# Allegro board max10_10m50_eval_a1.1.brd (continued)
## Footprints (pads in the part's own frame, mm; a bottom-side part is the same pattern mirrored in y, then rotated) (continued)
QFN56
  oval 0.813x0.279 smd: 1(-3.9,3.25) 2(-3.9,2.75) 3(-3.9,2.25) 4(-3.9,1.75) 5(-3.9,1.25) 6(-3.9,0.75) 7(-3.9,0.25) 8(-3.9,-0.25) 9(-3.9,-0.75) 10(-3.9,-1.25) 11(-3.9,-1.75) 12(-3.9,-2.25) 13(-3.9,-2.75) 14(-3.9,-3.25) 29(3.9,-3.25) 30(3.9,-2.75) 31(3.9,-2.25) 32(3.9,-1.75) 33(3.9,-1.25) 34(3.9,-0.75) 35(3.9,-0.25) 36(3.9,0.25) 37(3.9,0.75) 38(3.9,1.25) 39(3.9,1.75) 40(3.9,2.25) 41(3.9,2.75) 42(3.9,3.25)
  oval 0.279x0.813 smd: 15(-3.25,-3.9) 16(-2.75,-3.9) 17(-2.25,-3.9) 18(-1.75,-3.9) 19(-1.25,-3.9) 20(-0.75,-3.9) 21(-0.25,-3.9) 22(0.25,-3.9) 23(0.75,-3.9) 24(1.25,-3.9) 25(1.75,-3.9) 26(2.25,-3.9) 27(2.75,-3.9) 28(3.25,-3.9) 43(3.25,3.9) 44(2.75,3.9) 45(2.25,3.9) 46(1.75,3.9) 47(1.25,3.9) 48(0.75,3.9) 49(0.25,3.9) 50(-0.25,3.9) 51(-0.75,3.9) 52(-1.25,3.9) 53(-1.75,3.9) 54(-2.25,3.9) 55(-2.75,3.9) 56(-3.25,3.9)
  rect 5.842x5.842 smd: 57(0,0)
SENSE
  rect 0.305x0.406 smd: 1(0,0.254) 2(0,-0.254)
SI510
  rect 1.55x1.95 smd: 1(-2.54,-2.1) 2(0,-2.1) 3(2.54,-2.1) 4(2.54,2.1) 5(0,2.1) 6(-2.54,2.1)
SO16_WIDE
  oval 0.6x2.2 smd: 1(-4.445,-4.599) 2(-3.175,-4.599) 3(-1.905,-4.599) 4(-0.635,-4.599) 5(0.635,-4.599) 6(1.905,-4.599) 7(3.175,-4.599) 8(4.445,-4.599) 9(4.445,4.599) 10(3.175,4.599) 11(1.905,4.599) 12(0.635,4.599) 13(-0.635,4.599) 14(-1.905,4.599) 15(-3.175,4.599) 16(-4.445,4.599)
SOT23-6L
  rect 0.6x1.4 smd: 1(-0.95,-1.3) 2(0,-1.3) 3(0.95,-1.3) 4(0.95,1.3) 5(0,1.3) 6(-0.95,1.3)
SOT-143
  rect 0.864x0.889 smd: 1(-0.914,0.762)
  rect 0.864x0.508 smd: 2(-0.914,-0.965) 3(0.94,-0.965) 4(0.94,0.965)
SW-PUSH-8X8
  rect 1.245x1.245 hole 0.762: 1(0,0)
  round 1.245 hole 0.762: 2(2.54,0) 3(5.08,0) 4(0,6.096) 5(2.54,6.096) 6(5.08,6.096)
TEST_PAD_SMT
  round 1.016 smd: 1(0,0)
TEST_PAD_SMT_10MIL
  round 0.254 smd: 1(0,0)
unnamed
  round 1.016 smd: 1(0,0)
unnamed#2
  round 6.35 hole 3.175: (0,0)
UQFN16
  rect 0.559x0.203 smd: 1(-1.05,1) 2(-1.05,0.6) 3(-1.05,0.2) 4(-1.05,-0.2) 5(-1.05,-0.6) 6(-1.05,-1) 9(1.05,-1) 10(1.05,-0.6) 11(1.05,-0.2) 12(1.05,0.2) 13(1.05,0.6) 14(1.05,1)
  rect 0.203x0.559 smd: 7(-0.2,-1.175) 8(0.2,-1.175) 15(0.2,1.175) 16(-0.2,1.175)
WURTH_MSOP8
  rect 1.016x0.406 smd: 1(-2.4,0.975) 2(-2.4,0.325) 3(-2.4,-0.325) 4(-2.4,-0.975) 5(2.4,-0.975) 6(2.4,-0.325) 7(2.4,0.325) 8(2.4,0.975)
WURTH_USB_MINI-B
  oval 1.016x1.143 hole 0.711: 1(-1.6,0.9) 2(-0.8,-0.3) 3(0,0.9) 4(0.8,-0.3) 5(1.6,0.9)
  oval 1.626x2.616 hole 0.914x1.905: 6(-3.65,0) 7(3.65,0) 8(-3.65,-4.65) 9(3.65,-4.65)
XTAL_FA-128
  rect 0.94x0.838 smd: 1(-0.725,-0.575) 2(0.725,-0.575) 3(0.725,0.575) 4(-0.725,0.575)

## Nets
1.2V_CORE: C221.1 C222.1 C223.1 C224.2 C225.2 C226.2 C227.2 C228.2 C229.2 C230.2 C231.2 L8.1 R238.2 U1.J7(VCCINT) U1.K11(VCC#K11) U1.K13(VCC#K13) U1.L10(VCC#L10) U1.L11(VCC#L11) U1.L12(VCC#L12) U1.M11(VCC#M11) U1.M12(VCC#M12) U1.M13(VCC#M13) U1.N10(VCC#N10) U1.N12(VCC#N12)
1.2V_CORE_ENABLE: C174.1 R252.1 R283.1 U21.18(ENABLE)
1.2V_CORE_POK: R239.1 U4.Y11(IOB4_36) U21.17(POK)
1.2V_CORE_SENSE: C112.2 C113.1 C114.1 C116.1 C248.1 C249.1 R238.1 R240.2 U21.4(VOUT#4) U21.5(VOUT#5) U21.6(VOUT#6) U21.7(VOUT#7)
1.2V_CORE_VFB: C112.1 R240.1 R243.2 U21.14(VFB)
1.2V_LED: D11.2(CATHODE) U4.Y9(IOB4_51)
1.2V_LED_R: D11.1(ANODE) R278.2
1.2V_VCCD_PLL: C121.1 C122.1 C145.2 C146.2 C147.2 C148.2 L8.2 U1.G7(VCCD_PLL3) U1.G16(VCCD_PLL2) U1.T7(VCCD_PLL1) U1.U16(VCCD_PLL4)
1.2V_VCCIO: C4.1 C6.1 C13.1 C14.1 C15.1 C16.1 C17.1 C18.1 C19.1 C20.1 C21.1 C22.1 C23.1 C24.1 C25.1 C118.1 C149.2 C194.1 C208.2 C209.1 C232.1 C233.2 C234.2 C235.2 C236.2 C241.1 C242.1 C244.1 C245.1 C246.1 C250.1 R7.1 R9.2 R10.2 R29.2 R30.2 R181.1 R182.1 R184.1 R185.1 R195.1 R196.1 R198.1 R202.1 R285.2 R315.2 U1.H16(VCCIO6#H16) U1.J17(VCCIO6#J17) U1.K16(VCCIO6#K16) U1.K17(VCCIO6#K17) U1.L16(VCCIO6#L16) U1.M17(VCCIO6#M17) U1.N16(VCCIO5#N16) U1.N17(VCCIO6#N17) U1.P16(VCCIO5#P16) U1.R16(VCCIO5#R16) U1.R17(VCCIO5#R17) U1.T17(VCCIO5#T17) U2.B5(VDD2#B5) U2.C7(VDDQ#C7) U2.C10(VDDQ#C10) U2.D2(VDD2#D2) U2.D5(VDDQ#D5) U2.E9(VDDQ#E9) U2.F1(VDDCA#F1) U2.F10(VDDQ#F10) U2.G1(VDD2#G1) U2.H1(VDDCA#H1) U2.H6(VDDQ#H6) U2.J6(VDDQ#J6) U2.J7(VDD2#J7) U2.K6(VDDQ#K6) U2.M10(VDDQ#M10) U2.N2(VDDCA#N2) U2.N9(VDDQ#N9) U2.P2(VDD2#P2) U2.P5(VDDQ#P5) U2.R7(VDDQ#R7) U2.R10(VDDQ#R10) U2.T5(VDD2#T5) U22.6(VOUT#6) U22.7(VOUT#7)
1.2V_VCCIO_ENABLE: C119.1 R241.1 R242.1 U22.10(ENABLE)
1.2V_VCCIO_VFB: C208.1 R285.1 R286.2 U22.4(VFB)
1.8V: C26.1 C27.1 C105.1 C106.1 C107.1 C196.1 C197.1 C217.1 C218.1 C219.1 C243.1 C247.1 L1.1 L2.1 L3.1 L6.2 R1.2 R64.1 R68.1 R89.1 R91.1 R92.1 R235.1 R241.2 R246.1 R279.2 R305.1 R308.1 U1.N6(VCCIO2#N6) U1.N7(VCCIO2#N7) U1.P7(VCCIO2#P7) U1.R6(VCCIO2#R6) U2.B6(VDD1#B6) U2.C1(VDD1#C1) U2.R1(VDD1#R1) U2.T6(VDD1#T6) U20.7(VOUT#7) U20.8(VOUT#8)
1.8V_AVDD: C52.1 C53.1 C54.1 C55.1 L3.2 R119.1 U3.15(AVDD#15) U3.19(AVDD#19) U3.25(AVDD#25)
1.8V_DVDD: C44.1 C45.1 C46.1 C47.1 C48.1 L1.2 U3.1(DVDD#1) U3.11(DVDD#11) U3.31(DVDD#31) U3.51(DVDD#51)
1.8V_ENABLE: C176.1 R257.2 U20.12(ENABLE)
1.8V_MIPITX: C29.1 J1.32 J1.33 R64.2
1.8V_OV10640: C171.1 J2.4 J2.5 R246.2
1.8V_PVDD: C49.1 C50.1 C51.1 L2.2 U3.12(PVDD) U3.13(BGVDD)
1.8V_SI5338: C88.1 L6.1 U14.20(VDDO0)
2.5V: C72.1 C73.1 C76.1 C77.1 C144.2 C211.1 C213.1 C216.2 C239.2 C251.1 J12.1 J12.2 J13.1 J13.2 R21.1 R24.1 R25.1 R137.1 R139.1 R200.2 R205.2 R236.1 R283.2 R290.2 U1.T9(VCCIO3#T9) U1.T10(VCCIO3#T10) U1.T11(VCCIO3#T11) U1.T12(VCCIO4#T12) U1.T13(VCCIO4#T13) U1.U8(VCCIO3#U8) U1.U9(VCCIO3#U9) U1.U11(VCCIO4#U11) U1.U12(VCCIO4#U12) U1.U14(VCCIO4#U14) U4.C9(VCCIO2#C9) U4.C10(VCCIO2#C10) U4.C11(VCCIO2#C11) U4.D10(VCCIO2#D10) U4.D11(VCCINT#D11) U4.K4(VCCINT#K4) U4.L17(VCCINT#L17) U4.U11(VCCINT#U11) U19.6(VOUT#6) U19.7(VOUT#7)
2.5V_CORE: L7.1 R236.2
2.5V_ENABLE: C175.1 R255.1 R282.1 U19.10(ENABLE)
2.5V_LED_R: D10.1(ANODE) R200.1
2.5V_VCCA: C108.1 C109.1 C124.2 C206.2 C237.2 C238.2 L7.2 R267.2 U1.H7(VCCA_ADC) U1.H8(VCCA3) U1.H15(VCCA2) U1.R8(VCCA1) U1.T15(VCCA4)
3.3V: C58.2 C63.1 C64.1 C65.1 C66.1 C67.1 C68.1 C69.1 C70.1 C74.1 C75.1 C78.1 C79.1 C80.1 C81.1 C91.1 C92.1 C93.1 C155.2 C156.2 C169.2 C170.1 J6.4 J7.4 J8.6 J8.12 J9.6 J9.12 J14.5(IO5) J14.6(IO6) L4.1 L5.2 L9.1 R27.1 R28.1 R61.1 R98.1 R99.1 R100.1 R101.1 R127.1 R128.1 R136.1 R138.1 R140.1 R141.1 R142.1 R145.2 R146.2 R147.1 R183.1 R186.1 R187.1 R188.1 R189.1 R190.1 R191.1 R192.1 R193.1 R194.1 R203.1 R204.1 R223.2 R239.2 R244.1 R245.1 R247.1 R248.2 R278.1 R281.2 R303.1 R306.1 R309.1 U1.F9(VCCIO8#F9) U1.F11(VCCIO8#F11) U1.F12(VCCIO7#F12) U1.F14(VCCIO7#F14) U1.G10(VCCIO8#G10) U1.G11(VCCIO8#G11) U1.G12(VCCIO7#G12) U1.G13(VCCIO7#G13) U1.G14(VCCIO7#G14) U1.K7(VCCIO1A#K7) U1.L6(VCCIO1A#L6) U1.L7(VCCIO1B#L7) U1.M6(VCCIO1B#M6) U4.J18(VCCIO3#J18) U4.K3(VCCIO1#K3) U4.K17(VCCIO3#K17) U4.K18(VCCIO3#K18) U4.L3(VCCIO1#L3) U4.L4(VCCIO1#L4) U4.L18(VCCIO3#L18) U4.M3(VCCIO1#M3) U4.U10(VCCIO4#U10) U4.V10(VCCIO4#V10) U4.V11(VCCIO4#V11) U4.V12(VCCIO4#V12) U5.4(VCC) U7.3(AVCC#3) U7.7(AVCC#7) U7.11(VCC#11) U7.17(VCC#17) U7.27(VCC#27) U7.32(VCC#32) U7.43(VCC#43) U7.55(VCC#55) U8.5(VDD) U9.5(VDD) U10.5(VDD) U11.5(VDD) U17.4(VOUT#4) U17.5(VOUT#5) U17.6(VOUT#6) U17.7(VOUT#7) U23.2(VCC)
3.3V_DVDD: C56.1 C57.1 L4.2 R120.2 R121.2 R122.2 U3.29(DVDD_3V)
3.3V_EN: C207.1 R279.1 R280.1 R284.2 U17.18(ENABLE)
3.3V_MIPITX: C30.1 J1.34 J1.35 J1.36 R61.2
3.3V_OV5640: C173.1 J3.16 R248.1
3.3V_OV10640: C172.1 J2.1 J2.2 J2.3 R247.2
3.3V_POK: R281.1 R282.2 U17.17(POK)
3.3V_SI510: C240.1 L9.2 R214.1 U15.6(VDD)
3.3V_SI5338: C82.1 C83.1 C84.1 C85.1 C86.1 L5.1 U14.7(VDD1) U14.11(VDDO3) U14.15(VDDO2) U14.16(VDDO1) U14.24(VDD2)
3.3V_VFB: C91.2 R223.1 R229.2 U17.14(VFB)
5V: C42.1 C43.1 D1.8 D2.8 J4.18(5V_VCC) J11.2 R114.2 R115.2 R199.1 R253.1 R254.1 R258.1 R260.1 R280.2 R289.1 R292.2 R293.1
5V_DCIN: J10.2 R217.1 R222.2 R224.2 U18.2(VDD) V1.2(SNS)
5V_FB: R226.1 R233.2 U18.12(FB)
5V_GATE: R225.2 R231.2 U18.9(GATE)
5V_IMON: R232.2 U18.13(IMON)
5V_LED_R: D9.1(ANODE) R199.2
5V_MONITOR: C94.1 C95.2 J11.1 R226.2 R227.2 R228.1 R292.1 U16.1(S1) U16.2(S2) U16.3(S3) U18.8(SOURCE)
5V_N: U18.15(SENSE-) V2.1(RSNS)
5V_OV: R224.1 R230.2 U18.4(OV)
5V_P: U18.16(SENSE+) V1.1(RSNS)
5V_PG: R227.1 U18.10(PG)
5V_R1.2CORE: C111.1 C120.1 R252.2 R253.2 U21.10(TST2) U21.11(TST1) U21.12(TST0) U21.16(AVIN) U21.19(PVIN#19) U21.20(PVIN#20)
5V_R1.2VCCIO: C115.1 C210.2 R242.2 R254.2 U22.11(AVIN) U22.12(PVIN)
5V_R1.8: C104.1 R257.1 R258.2 U20.9(VS2) U20.10(VS1) U20.11(VS0) U20.13(AVIN) U20.14(PVIN)
5V_R2.5: C212.2 C215.1 R255.2 R289.2 U19.11(AVIN) U19.12(PVIN)
5V_R3.3: C90.1 C96.1 R260.2 U17.10(TST2) U17.11(TST1) U17.12(TST0) U17.16(AVIN) U17.19(PVIN#19) U17.20(PVIN#20)
5V_UV: R264.2 U18.3(UV) U18.11(/FLT)
GND: C1.2 C3.2 C8.2 C9.2 C10.2 C11.2 C13.2 C14.2 C15.2 C16.2 C17.2 C18.2 C19.2 C20.2 C21.2 C22.2 C23.2 C24.2 C25.2 C26.2 C27.2 C28.2 C29.2 C30.2 C31.2 C32.2 C33.2 C34.2 C35.2 C36.2 C37.2 C38.2 C39.2 C40.2 C41.2 C42.2 C43.2 C44.2 C45.2 C46.2 C47.2 C48.2 C49.2 C50.2 C51.2 C52.2 C53.2 C54.2 C55.2 C56.2 C57.2 C58.1 C59.2 C60.2 C61.2 C62.2 C63.2 C64.2 C65.2 C66.2 C67.2 C68.2 C69.2 C70.2 C71.2 C72.2 C73.2 C74.2 C75.2 C76.2 C77.2 C78.2 C79.2 C80.2 C81.2 C82.2 C83.2 C84.2 C85.2 C86.2 C87.1 C88.2 C89.1 C90.2 C92.2 C93.2 C94.2 C95.1 C96.2 C97.2 C98.1 C99.2 C104.2 C106.2 C107.2 C108.2 C109.2 C111.2 C113.2 C114.2 C115.2 C116.2 C118.2 C119.2 C120.2 C121.2 C122.2 C124.1 C144.1 C145.1 C146.1 C147.1 C148.1 C149.1 C155.1 C156.1 C169.1 C170.2 C171.2 C172.2 C173.2 C174.2 C175.2 C176.2 C194.2 C196.2 C197.2 C206.1 C207.2 C209.2 C210.1 C211.2 C212.1 C213.2 C215.2 C217.2 C218.2 C219.2 C220.2 C221.2 C222.2 C223.2 C224.1 C225.1 C226.1 C227.1 C228.1 C229.1 C230.1 C231.1 C232.2 C233.1 C234.1 C235.1 C236.1 C237.1 C238.1 C239.1 C240.2 C243.2 C244.2 C245.2 C246.2 C247.2 C248.2 C249.2 C250.2 C251.2 D1.7 D2.7 D9.2(CATHODE) D10.2(CATHODE) J1.3 J1.4 J1.8 J1.15 J1.18 J1.21 J1.24 J1.27 J1.30 J1.31 J1.G1(SP1) J1.G2(SP2) J1.G3(SP3) J1.G4(SP4) J2.6 J2.7 J2.10 J2.13 J2.16 J2.19 J2.22 J2.29 J2.33 J2.34 J2.G1(SP1) J2.G2(SP2) J2.G3(SP3) J2.G4(SP4) J3.3 J3.4 J3.7 J3.10 J3.17 J3.18 J4.2(TMDS_DATA_SHLD2) J4.5(TMDS_DATA_SHLD1) J4.8(TMDS_DATA_SHLD0) J4.11(TMDS_DATA_SHLD_CLK) J4.17(DDC_CEC_GND) J4.G1(MTG1) J4.G2(MTG2) J4.G3(MTG3) J4.G4(MTG4) J5.5(GND) J6.2 J6.10 J7.10 J8.5 J8.11 J9.5 J9.11 J10.1 J10.3 J12.7 J12.8 J12.13 J12.14 J12.19 J12.20 J13.7 J13.8 J13.13 J13.14 J13.19 J13.20 J14.11(IO11) J14.12(IO12) R2.1 R8.1 R11.1 R12.1 R18.1 R20.1 R22.1 R23.1 R31.1 R32.1 R34.1 R35.2 R38.2 R39.2 R43.1 R45.1 R51.2 R52.2 R55.1 R57.1 R63.2 R66.1 R111.1 R112.1 R113.1 R116.1 R117.2 R118.2 R124.2 R125.1 R126.2 R134.1 R135.1 R144.1 R180.1 R221.1 R228.2 R229.1 R230.1 R232.1 R233.1 R243.1 R269.1 R284.1 R286.1 R291.1 R315.1 S1.1 S1.2 S2.1 S2.2 S3.1 S3.2 S4.1 S4.2 S6.1 S6.2 S7.1 S7.2 SW1.1(A1) SW1.2(A2) SW1.3(A3) SW1.4(A4) SW2.1(A1) SW2.2(A2) SW2.3(A3) SW2.4(A4) SW3.1(NO1) SW3.6(NO2) TP1.1(TP) TP2.1(TP) TP3.1(TP) TP4.1(TP) TP5.1(TP) TP6.1(TP) U1.A1(GND#A1) U1.A22(GND#A22) U1.AA4(GND#AA4) U1.AA18(GND#AA18) U1.AB1(GND#AB1) U1.AB22(GND#AB22) U1.B6(GND#B6) U1.B9(GND#B9) U1.B13(GND#B13) U1.B18(GND#B18) U1.B20(DIFFIO_RX_R62P) U1.B21(DIFFIO_RX_R60N) U1.C20(DIFFIO_RX_R56P) U1.C21(TBD6) U1.D4(GND#D4) U1.D11(GND#D11) U1.D16(GND#D16) U1.D19(DIFFIO_RX_R56N) U1.D20(GND#D20) U1.E2(GND#E2) U1.E5(NC1) U1.E6(DIFFIO_RX_T52N/PLL_T_CLKOUTN) U1.E7(GND#E7) U1.E17(DIFFIO_RX_R59N) U1.E19(DIFFIO_RX_R53P) U1.E20(DIFFIO_RX_R54N) U1.F6(NC2) U1.F10(GND#F10) U1.F13(GND#F13) U1.F17(DIFFIO_RX_R59P) U1.F18(DIFFIO_RX_R53N) U1.F19(DIFFIO_RX_R54P) U1.F20(DIFFIO_RX_R48N) U1.F21(DIFFIO_RX_R48P) U1.G5(ANAIN1) U1.G6(GND#G6) U1.G8(GND#G8) U1.G15(GND#G15) U1.G17(DIFFIO_RX_R69N/PLL_R_CLKOUTN) U1.G18(GND#G18) U1.G19(DIFFIO_RX_R42N) U1.G20(DIFFIO_RX_R42P) U1.G21(GND#G21) U1.H5(REFGND) U1.H11(DIFFIO_RX_T40N/CLK5N) U1.H17(DIFFIO_RX_R69P/PLL_R_CLKOUTP) U1.J2(GND#J2) U1.J5(ANAIN2) U1.J6(GND#J6) U1.J8(DIFFIO_RX_L3N/ADC1IN3) U1.J9(DIFFIO_RX_L3P/ADC1IN4) U1.J16(GND#J16) U1.J19(GND#J19) U1.J20(DIFFIO_RX_R64P/DQ3R) U1.K3(GND#K3) U1.K4(DIFFIO_RX_L8N/ADC2IN7) U1.K5(DIFFIO_RX_L7N/ADC1IN7) U1.K6(DIFFIO_RX_L7P/ADC1IN8) U1.K10(GND#K10) U1.K12(GND#K12) U1.L5(GND#L5) U1.L13(GND#L13) U1.L17(GND#L17) U1.L19(DIFFIO_RX_R52P/DQ2R) U1.L21(GND#L21) U1.L22(DIFFIO_RX_R34N) U1.M7(GND#M7) U1.M8(DIFFIO_RX_L36N/CLK1N) U1.M10(GND#M10) U1.M16(GND#M16) U1.M19(GND#M19) U1.M21(DIFFIO_RX_R34P) U1.M22(DIFFIO_RX_R35N) U1.N4(DIFFIO_RX_L28N/CLK0N) U1.N11(GND#N11) U1.N13(GND#N13) U1.N15(DIFFIO_RX_R38N/CLK2N) U1.N21(DIFFIO_RX_R35P) U1.P2(GND#P2) U1.P3(DIFFIO_RX_L38N/DPCLK0) U1.P6(GND#P6) U1.P17(GND#P17) U1.P18(DIFFIO_RX_R32N/DQSN1R) U1.P19(DIFFIO_RX_R33P/DQ1R) U1.P20(DIFFIO_RX_R33N/DQ1R) U1.R3(DIFFIO_RX_L38P/DPCLK1) U1.R19(GND#R19) U1.R21(GND#R21) U1.R22(TBD5) U1.T4(GND#T4) U1.T5(DIFFIO_RX_L59N/PLL_L_CLKOUTN) U1.T6(DIFFIO_RX_L59P/PLL_L_CLKOUTP) U1.T8(GND#T8) U1.T14(GND#T14) U1.T16(GND#T16) U1.T20(DIFFIO_RX_R28P/DQ1R) U1.U10(GND#U10) U1.U13(GND#U13) U1.U21(DIFFIO_RX_R29P) U1.U22(DIFFIO_RX_R29N) U1.V2(GND#V2) U1.V6(GND#V6) U1.V18(DIFFIO_RX_R19P) U1.V19(GND#V19) U1.V20(DIFFIO_RX_R23P) U1.W21(GND#W21) U1.Y9(GND#Y9) U1.Y12(GND#Y12) U1.Y15(GND#Y15) U2.C2(VSS#C2) U2.C5(VSS#C5) U2.C6(VSSQ#C6) U2.C9(VSSQ#C9) U2.D1(VSS#D1) U2.D10(VSSQ#D10) U2.E1(VSSCA#E1) U2.E10(VSSQ#E10) U2.F5(VSSQ#F5) U2.G10(VSSQ#G10) U2.H2(VSS#H2) U2.J1(VSSCA#J1) U2.J5(VSSQ#J5) U2.J8(VSS#J8) U2.L10(VSSQ#L10) U2.M5(VSSQ#M5) U2.N1(VSSCA#N1) U2.N10(VSSQ#N10) U2.P1(VSS#P1) U2.P10(VSSQ#P10) U2.R2(VSS#R2) U2.R5(VSS#R5) U2.R6(VSSQ#R6) U2.R9(VSSQ#R9) U3.65(EPAD_GND) U4.C8(GNDIO#C8) U4.C12(GNDIO#C12) U4.C13(GNDIO#C13) U4.D9(GNDIO#D9) U4.D12(GNDINT#D12) U4.H3(GNDIO#H3) U4.H18(GNDIO#H18) U4.J3(GNDIO#J3) U4.J4(GNDINT#J4) U4.J17(GNDIO#J17) U4.M4(GNDIO#M4) U4.M17(GNDINT#M17) U4.M18(GNDIO#M18) U4.N3(GNDIO#N3) U4.N18(GNDIO#N18) U4.U9(GNDIO#U9) U4.U12(GNDINT#U12) U4.V8(GNDIO#V8) U4.V9(GNDIO#V9) U4.V13(GNDIO#V13) U5.1(GND) U6.3(GND) U7.6(AGND#6) U7.10(AGND#10) U7.12(GND#12) U7.14(RESERVED) U7.26(GND#26) U7.28(GND#28) U7.41(GND#41) U7.53(GND#53) U7.56(GND#56) U7.57(EXPOSED_PAD) U8.2(GND) U9.2(GND) U10.2(GND) U11.2(GND) U14.3(CLKIN) U14.4(I2C_LSB) U14.6(FDBK_N) U14.23(RSVD_GND) U14.25(EPAD) U15.3(GND) U17.2(PGND#2) U17.3(PGND#3) U17.8(PGND#8) U17.9(PGND#9) U17.15(AGND) U17.25(PGND#25) U17.26(PGND#26) U18.7(GND) U19.2(PGND) U19.5(AGND) U20.2(PGND#2) U20.3(PGND#3) U20.6(AGND) U21.2(PGND#2) U21.3(PGND#3) U21.8(PGND#8) U21.9(PGND#9) U21.15(AGND) U21.25(PGND#25) U21.26(PGND#26) U22.2(PGND) U22.5(AGND) U23.10(VSS) Y1.2 Y1.4 Y2.2 Y2.4
GND_EARTH: C59.1 J5.6(SHELL1) J5.7(SHELL2) J5.8(SHELL3) J5.9(SHELL4) R125.2
VBUS_5V: C220.1 J5.1(VBUS) J11.3 R133.1 R293.2
24M_XTALIN: C60.1 U7.5(XTALIN) Y1.1
24M_XTALOUT: C61.1 U7.4(XTALOUT) Y1.3
ADC_VREF: R267.1 U1.H6(ADC_VREF)
C_USB_MAX_TCK: J6.1 R129.1 R135.2 U4.W2(TCK)
C_USB_MAX_TDI: J6.9 R130.1 U4.U2(TDI)
C_USB_MAX_TDO: J6.3 R131.1 U4.V2(TDO)
C_USB_MAX_TMS: J6.5 R132.1 R136.2 U4.T3(TMS)
CEC_CLK: R111.2 U3.32(CEC_CLK)
CEC_IO: R112.2 U3.30(CEC)
CLK24M: R213.2 U1.M9(DIFFIO_RX_L36P/CLK1P)
CLK24M_R: R213.1 U14.22(CLK0A)
CLK50M_EN: R214.2 U15.2(OE)
CLK50M_MAX10: R215.2 U1.J10(DIFFIO_RX_T40P/CLK5P)
CLK50M_MAX10_R: R215.1 U15.4(CLKP)
CLK50M_MAXII: R216.2 U4.L1(IOB1/GCLK1)
CLK50M_MAXII_R: R216.1 U15.5(CLKN)
CLK100M_LPDDR2: R208.2 U1.E10(DIFFIO_RX_T38N/CLK4N)
CLK100M_LPDDR2_BK: R17.2 R207.2
CLK100M_LPDDR2_BK_R: R207.1 U14.9(CLK3B)
CLK100M_LPDDR2_BKDIV: R17.1 R18.2 U1.N14(DIFFIO_RX_R38P/CLK2P)
CLK100M_LPDDR2_R: R208.1 U14.10(CLK3A)
CLK125M: R19.2 R210.2
CLK125M_DIV_R: R19.1 R20.2 R270.1
CLK125M_R: R210.1 U14.13(CLK2B)
CLKOUT_LVDS_N: J12.18 R170.1 U1.W17(DIFFIO_TX_RX_B57N/PLL_B_CLKOUTN)
CLKOUT_LVDS_P: J12.16 R170.2 U1.V17(DIFFIO_TX_RX_B57P/PLL_B_CLKOUTP)
EXT_JTAG_TCK: R143.1 R144.2 R148.2 U4.M20(IOB3/GCLK2)
EXT_JTAG_TCK_R: J7.1 R148.1
EXT_JTAG_TDI: R146.1 R152.2 U4.H17(IOB3_21)
EXT_JTAG_TDI_R: J7.9 R152.1
EXT_JTAG_TDO: R149.2 U4.F17(IOB3_13)
EXT_JTAG_TDO_R: J7.3 R149.1
EXT_JTAG_TMS: R145.1 R150.2 U4.G17(IOB3_17)
EXT_JTAG_TMS_R: J7.5 R150.1
FLASH_CLK: U1.A9(DIFFIO_RX_T31P) U23.16(C)
FLASH_CSN: R245.2 U1.A8(DIFFIO_RX_T29N) U23.7(S#)
FLASH_D0: U1.C9(DIFFIO_RX_T30N) U23.15(DQ0)
FLASH_D1: U1.C10(DIFFIO_RX_T26N) U23.8(DQ1)
FLASH_D2: U1.C11(DIFFIO_RX_T26P) U23.9(DQ2/VPP/W#)
FLASH_D3: U1.A7(DIFFIO_RX_T29P) U23.1(DQ3/HOLD#)
FLASH_RESETN: R244.2 R249.1 R250.1 U23.3(RESET)
FLASH_RESETN_MAX10: R250.2 U1.B8(DIFFIO_RX_T31N)
FLASH_RESETN_MAXII: R249.2 U4.U14(IOB4_2)
FX2_D_N: J5.2(D-) U6.2(D-) U7.9(DMINUS)
FX2_D_P: J5.3(D+) U6.1(D+) U7.8(DPLUS)
FX2_FLAGA: U4.H4(IOB1_24) U7.29(CTL0)
FX2_FLAGB: U4.H1(IOB1_22) U7.30(CTL1)
FX2_FLAGC: U4.J1(IOB1_25) U7.31(CTL2)
FX2_PA0: U4.N4(IOB1_33) U7.33(PA0)
FX2_PA1: U4.P4(IOB1_37) U7.34(PA1)
FX2_PA2: U4.R4(IOB1_41) U7.35(PA2)
FX2_PA3: U4.T4(IOB1_44) U7.36(PA3)
FX2_PA4: U4.M1(IOB1_29) U7.37(PA4)
FX2_PA5: U4.N1(IOB1_31) U7.38(PA5)
FX2_PA6: U4.P1(IOB1_34) U7.39(PA6)
FX2_PA7: U4.R1(IOB1_38) U7.40(PA7)
FX2_PB0: U4.D1(IOB1_6) U7.18(PB0)
FX2_PB1: U4.E1(IOB1_10) U7.19(PB1)
FX2_PB2: U4.F1(IOB1_14) U7.20(PB2)
FX2_PB3: U4.G1(IOB1_18) U7.21(PB3)
FX2_PB4: U4.D4(IOB1_9) U7.22(PB4)
FX2_PB5: U4.E4(IOB1_13) U7.23(PB5)
FX2_PB6: U4.F4(IOB1_17) U7.24(PB6)
FX2_PB7: U4.G4(IOB1_21) U7.25(PB7)
FX2_PD0: R129.2 U7.45(PD0)
FX2_PD1: R132.2 U7.46(PD1)
FX2_PD2: R130.2 U7.47(PD2)
FX2_PD3: R131.2 U7.48(PD3)
FX2_PD4: U4.Y3(IOB4_45) U7.49(PD4)
FX2_PD5: U4.Y2(IOB4_44) U7.50(PD5)
FX2_PD6: U4.Y4(IOB4_46) U7.51(PD6)
FX2_PD7: U4.Y5(IOB4_47) U7.52(PD7)
FX2_RESETN: R126.1 U4.Y13(IOB4/DEV_CLRN) U5.2(R\E\S\E\T\) U7.42(R\E\S\E\T\)
FX2_SCL: R127.2 U4.B1(IOB1_1) U7.15(SCL)
FX2_SDA: R123.1 R128.2 U7.16(SDA)
FX2_SLRDN: U4.Y6(IOB4_48) U7.1(RDY0)
FX2_SLWRN: U4.Y7(IOB4_49) U7.2(RDY1)
FX2_WAKEUP: C62.1 R133.2 R134.2 U7.44(WAKEUP)
HDMI_DDCSCL: D2.5 J4.15(SCL) R115.1 U3.33(DDCSCL)
HDMI_DDCSDA: D2.6 J4.16(SDA) R114.1 U3.34(DDCSDA)
HDMI_HPD: D1.5 J4.19(HOT_PLUG_DETECT) R117.1 U3.16(HPD)
HDMI_HSYNC: U1.H13(DIFFIO_RX_T22P) U3.64(HSYNC)
HDMI_INTR: R122.1 U1.A18(DIFFIO_RX_T10P) U3.28(INT)
HDMI_IREF: R116.2 U3.14(R_EXT)
HDMI_SCL: R121.1 U1.C16(DIFFIO_RX_T15P) U3.35(SCL)
HDMI_SDA: R120.1 U1.B17(DIFFIO_RX_T7N) U3.36(SDA)
HDMI_VIDEO_CLK: R113.2 U1.D6(DIFFIO_RX_T52P/PLL_T_CLKOUTP) U3.53(CLK)
HDMI_VIDEO_DATA_EN: U1.J13(DIFFIO_RX_T17N) U3.63(DE)
HDMI_VIDEO_DIN0: U1.J12(DIFFIO_RX_T22N) U3.62(D0)
HDMI_VIDEO_DIN1: U1.D13(DIFFIO_RX_T21N) U3.61(D1)
HDMI_VIDEO_DIN2: U1.E12(DIFFIO_RX_T21P) U3.60(D2)
HDMI_VIDEO_DIN3: U1.E13(DIFFIO_RX_T20N) U3.59(D3)
HDMI_VIDEO_DIN4: U1.D12(DIFFIO_RX_T24N) U3.58(D4)
HDMI_VIDEO_DIN5: U1.B16(DIFFIO_RX_T16P) U3.57(D5)
HDMI_VIDEO_DIN6: U1.A16(DIFFIO_RX_T16N) U3.56(D6)
HDMI_VIDEO_DIN7: U1.C15(DIFFIO_RX_T15N) U3.55(D7)
HDMI_VIDEO_DIN8: U1.B14(DIFFIO_RX_T19N) U3.54(D8)
HDMI_VIDEO_DIN9: U1.A14(DIFFIO_RX_T19P) U3.52(D9)
HDMI_VIDEO_DIN10: U1.A13(DIFFIO_RX_T23P) U3.50(D10)
HDMI_VIDEO_DIN11: U1.B12(DIFFIO_RX_T27P) U3.49(D11)
HDMI_VIDEO_DIN12: U1.A12(DIFFIO_RX_T23N) U3.48(D12)
HDMI_VIDEO_DIN13: U1.C12(DIFFIO_RX_T24P) U3.47(D13)
HDMI_VIDEO_DIN14: U1.A11(DIFFIO_RX_T25P) U3.46(D14)
HDMI_VIDEO_DIN15: U1.B11(DIFFIO_RX_T27N) U3.45(D15)
HDMI_VIDEO_DIN16: U1.A10(DIFFIO_RX_T25N) U3.44(D16)
HDMI_VIDEO_DIN17: U1.C14(DIFFIO_RX_T18P) U3.43(D17)
HDMI_VIDEO_DIN18: U1.E14(DIFFIO_RX_T9N) U3.42(D18)
HDMI_VIDEO_DIN19: U1.D14(DIFFIO_RX_T20P) U3.41(D19)
HDMI_VIDEO_DIN20: U1.C13(DIFFIO_RX_T18N) U3.40(D20)
HDMI_VIDEO_DIN21: U1.E15(DIFFIO_RX_T1N) U3.39(D21)
HDMI_VIDEO_DIN22: U1.F15(DIFFIO_RX_T5N) U3.38(D22)
HDMI_VIDEO_DIN23: U1.D15(DIFFIO_RX_T9P) U3.37(D23)
HDMI_VSYNC: U1.H14(DIFFIO_RX_T17P) U3.2(VSYNC)
I2C_MAXII_SCL: R139.2 R206.1 U4.A7(IOB2_18)
I2C_MAXII_SDA: R137.2 R209.1 U4.A6(IOB2_17)
JTAG_LOCK: R151.2 U4.Y8(IOB4_50)
JTAG_LOCK_R: J7.7 R151.1
JTAG_SAFE: U1.K1(DIFFIO_RX_L25N) U4.Y17(IOB4_41)
LPDDR2_CA0: U1.J22(DIFFIO_RX_R41P) U2.P3(CA0)
LPDDR2_CA1: U1.J21(DIFFIO_RX_R41N) U2.N3(CA1)
LPDDR2_CA2: U1.F22(DIFFIO_RX_R43N) U2.M3(CA2)
LPDDR2_CA3: U1.H21(DIFFIO_RX_R39N) U2.M2(CA3)
LPDDR2_CA4: U1.H22(DIFFIO_RX_R39P) U2.M1(CA4)
LPDDR2_CA5: U1.D22(DIFFIO_RX_R49P) U2.G2(CA5)
LPDDR2_CA6: U1.C22(DIFFIO_RX_R49N) U2.F2(CA6)
LPDDR2_CA7: U1.E22(DIFFIO_RX_R45P) U2.F3(CA7)
LPDDR2_CA8: U1.A21(DIFFIO_RX_R62N) U2.E3(CA8)
LPDDR2_CA9: U1.B22(DIFFIO_RX_R60P) U2.E2(CA9)
LPDDR2_CK: R33.2 U1.D18(DIFFIO_RX_R70P/CK_6) U2.J3(CK)
LPDDR2_CKE: R31.2 U1.E21(DIFFIO_RX_R45N) U2.K1(CKE)
LPDDR2_CKN: R33.1 U1.E18(DIFFIO_RX_R70N/CK#_6) U2.H3(CK#)
LPDDR2_CSN: U1.G22(DIFFIO_RX_R43P) U2.L1(CS#)
LPDDR2_DM0: U1.N19(DIFFIO_RX_R46N/DM2R) U2.K5(DM0)
LPDDR2_DM1: U1.J15(DIFFIO_RX_R61N/DM3R) U2.H5(DM1)
LPDDR2_DQ0: U1.N18(DIFFIO_RX_R46P/DQ2R) U2.N8(DQ0)
LPDDR2_DQ1: U1.N20(DIFFIO_RX_R47N/DQ2R) U2.M8(DQ1)
LPDDR2_DQ2: U1.M20(DIFFIO_RX_R47P/DQ2R) U2.M7(DQ2)
LPDDR2_DQ3: U1.M14(DIFFIO_RX_R44N/DQ2R) U2.M9(DQ3)
LPDDR2_DQ4: U1.M18(DIFFIO_RX_R51P/DQ2R) U2.M6(DQ4)
LPDDR2_DQ5: U1.M15(DIFFIO_RX_R44P/DQ2R) U2.L7(DQ5)
LPDDR2_DQ6: U1.L20(DIFFIO_RX_R52N/DQ2R) U2.L8(DQ6)
LPDDR2_DQ7: U1.L18(DIFFIO_RX_R51N/DQ2R) U2.L9(DQ7)
LPDDR2_DQ8: U1.K20(DIFFIO_RX_R58N/DQ3R) U2.G9(DQ8)
LPDDR2_DQ9: U1.K19(DIFFIO_RX_R58P/DQ3R) U2.G8(DQ9)
LPDDR2_DQ10: U1.K18(DIFFIO_RX_R57P/DQ3R) U2.G7(DQ10)
LPDDR2_DQ11: U1.H19(DIFFIO_RX_R63P/DQ3R) U2.F6(DQ11)
LPDDR2_DQ12: U1.H20(DIFFIO_RX_R64N/DQ3R) U2.F9(DQ12)
LPDDR2_DQ13: U1.H18(DIFFIO_RX_R63N/DQ3R) U2.F7(DQ13)
LPDDR2_DQ14: U1.J14(DIFFIO_RX_R61P/DQ3R) U2.F8(DQ14)
LPDDR2_DQ15: U1.J18(DIFFIO_RX_R57N/DQ3R) U2.E8(DQ15)
LPDDR2_DQS0: U1.L14(DIFFIO_RX_R50P/DPCLK3/DQS2R) U2.L6(DQS0)
LPDDR2_DQS0N: U1.L15(DIFFIO_RX_R50N/DPCLK2/DQSN2R) U2.L5(DQS0#)
LPDDR2_DQS1: U1.K14(DIFFIO_RX_R55P/DQS3R) U2.G6(DQS1)
LPDDR2_DQS1N: U1.K15(DIFFIO_RX_R55N/DQSN3R) U2.G5(DQS1#)
LPDDR2_VREFCA: C10.1 C241.2 R29.1 R32.2 U2.G3(VREFCA)
LPDDR2_VREFDQ: C11.1 C242.2 R30.1 R34.2 U2.J9(VREFDQ)
LPDDR2_ZQ: R35.1 U2.D3(ZQ)
MAX10_BYPASSN: R192.2 SW2.5(B4) U4.B20(IOB3_1)
MAX10_CONF_DONE: R28.2 U1.F8(DIFFIO_RX_T50N/CONF_DONE) U4.U13(IOB4_1)
MAX10_CONFIG_SEL: R191.2 SW2.6(B3) U1.H10(BOOT_SEL)
MAX10_JTAG_TCK: R23.2 U1.G2(DIFFIO_RX_L17P/TCK) U4.A15(IOB2_7)
MAX10_JTAG_TDI: R25.2 U1.L4(DIFFIO_RX_L18N/TDI) U4.A13(IOB2_5)
MAX10_JTAG_TDO: R314.1 U4.A12(IOB2_4)
MAX10_JTAG_TDO_3V3: R314.2 U1.M5(DIFFIO_RX_L18P/TDO)
MAX10_JTAG_TMS: R24.2 U1.H2(DIFFIO_RX_L17N/TMS) U4.A16(IOB2_8)
MAX10_JTAGEN: R21.2 R22.2 U1.K9(DIFFIO_RX_L15P/JTAGEN) U4.A14(IOB2_6)
MAX10_NCONFIG: R203.2 S6.3 S6.4 U1.H9(NCONFIG)
MAX10_NSTATUS: R27.2 U1.G9(DIFFIO_RX_T50P/NSTATUS) U4.U16(IOB4_4)
MAX10_RDN: R8.2 U1.U17(DIFFIO_RX_R1N/RDN)
MAX10_RESETN: R204.2 S7.3 S7.4 U1.D9(DIFFIO_RX_T42N/DEV_CLRN)
MAX10_RUP: R7.2 U1.U18(DIFFIO_RX_R1P/RUP)
MAX_SDA: R123.2 U4.C1(IOB1_2)
MAXII_CONF_DONE: D8.2(CATHODE) U4.Y10(IOB4_35)
MAXII_CONF_DONE_R: D8.1(ANODE) R194.2
MIPI_TX_CLK24MHZ: J1.11 R212.2
MIPI_TX_CLK24MHZ_R: R212.1 U14.21(CLK0B)
MIPI_TX_CLK_HS_N: R42.2 TP10.1(TP) U1.R1(DIFFIO_RX_L60N)
MIPI_TX_CLK_HS_P: R41.2 TP8.1(TP) U1.R2(DIFFIO_RX_L60P)
MIPI_TX_CLK_LP_N: R47.2 TP11.1(TP) U1.Y1(DIFFIO_RX_B4N)
MIPI_TX_CLK_LP_P: R37.2 TP7.1(TP) U1.Y2(DIFFIO_RX_B4P)
MIPI_TX_CLKN: J1.25 R42.1 R43.2 R47.1
MIPI_TX_CLKP: J1.26 R37.1 R38.1 R41.1
MIPI_TX_CMOS_RST_1V8: R308.2 R312.2 U1.T3(DIFFIO_RX_L43N)
MIPI_TX_CMOS_RST_3V3: R309.2 R313.2 U1.B10(DIFFIO_RX_T30P)
MIPI_TX_CMOS_RST_IO: C28.1 J1.14 R312.1 R313.1
MIPI_TX_CMOS_SCLK: J1.12 R294.1 R302.1
MIPI_TX_CMOS_SCLK_1V8: R68.2 R294.2 U1.N3(DIFFIO_RX_L37N)
MIPI_TX_CMOS_SCLK_3V3: R302.2 R303.2 U1.J11(DIFFIO_RX_T28N)
MIPI_TX_CMOS_SDATA: J1.13 R304.1 R307.1
MIPI_TX_CMOS_SDATA_1V8: R305.2 R307.2 U1.N2(DIFFIO_RX_L37P)
MIPI_TX_CMOS_SDATA_3V3: R304.2 R306.2 U1.H12(DIFFIO_RX_T28P)
MIPI_TX_DATA1N: J1.28 R54.1 R55.2 R58.1
MIPI_TX_DATA1P: J1.29 R48.1 R50.1 R51.1
MIPI_TX_DATA2N: J1.22 R65.1 R66.2 R67.2
MIPI_TX_DATA2P: J1.23 R60.1 R62.1 R63.1
MIPI_TX_DATA3N: J1.19 R44.1 R45.2 R46.1
MIPI_TX_DATA3P: J1.20 R36.1 R39.1 R40.1
MIPI_TX_DATA4N: J1.16 R56.1 R57.2 R59.1
MIPI_TX_DATA4P: J1.17 R49.1 R52.1 R53.1
MIPI_TX_DATA_HS_N1: R54.2 TP15.1(TP) U1.P1(DIFFIO_RX_L42N)
MIPI_TX_DATA_HS_N2: R65.2 TP21.1(TP) U1.T1(DIFFIO_RX_L40N)
MIPI_TX_DATA_HS_N3: R44.2 TP27.1(TP) U1.U1(DIFFIO_RX_L44N)
MIPI_TX_DATA_HS_N4: R56.2 TP33.1(TP) U1.W1(DIFFIO_RX_L48N)
MIPI_TX_DATA_HS_P1: R50.2 TP14.1(TP) U1.N1(DIFFIO_RX_L42P)
MIPI_TX_DATA_HS_P2: R62.2 TP20.1(TP) U1.T2(DIFFIO_RX_L40P)
MIPI_TX_DATA_HS_P3: R40.2 TP26.1(TP) U1.V1(DIFFIO_RX_L44P)
MIPI_TX_DATA_HS_P4: R53.2 TP32.1(TP) U1.W2(DIFFIO_RX_L48P)
MIPI_TX_DATA_LP_N1: R58.2 TP16.1(TP) U1.V4(DIFFIO_RX_B2N)
MIPI_TX_DATA_LP_N2: R67.1 TP22.1(TP) U1.AB2(DIFFIO_RX_B12N)
MIPI_TX_DATA_LP_N3: R46.2 TP28.1(TP) U1.AA5(DIFFIO_RX_B17N)
MIPI_TX_DATA_LP_N4: R59.2 TP34.1(TP) U1.AB6(DIFFIO_RX_B19N)
MIPI_TX_DATA_LP_P1: R48.2 TP13.1(TP) U1.V5(DIFFIO_RX_B2P)
MIPI_TX_DATA_LP_P2: R60.2 TP19.1(TP) U1.AB3(DIFFIO_RX_B12P)
MIPI_TX_DATA_LP_P3: R36.2 TP25.1(TP) U1.AB5(DIFFIO_RX_B17P)
MIPI_TX_DATA_LP_P4: R49.2 TP31.1(TP) U1.AB7(DIFFIO_RX_B19P)
MIPI_TX_GPIO1: R273.1 U1.U3(DIFFIO_RX_L46N)
MIPI_TX_GPIO1_IO: J1.10 R273.2
MIPI_TX_GPIO2: R274.1 U1.U2(DIFFIO_RX_L43P)
MIPI_TX_GPIO2_IO: J1.9 R274.2
MIPI_TX_GPIO3: R275.1 U1.U4(DIFFIO_RX_L45N)
MIPI_TX_GPIO3_IO: J1.7 R275.2
MIPI_TX_GPIO4: R276.1 U1.U5(DIFFIO_RX_L45P)
MIPI_TX_GPIO4_IO: J1.6 R276.2
MIPI_TX_GPIO5: R277.1 U1.V3(DIFFIO_RX_L46P)
MIPI_TX_GPIO5_IO: J1.5 R277.2
OV5640_CAM_PWRON: C38.1 J3.11 R98.2 U1.L2(DIFFIO_RX_L19P)
OV5640_CAM_RESETB: C39.1 J3.15 R99.2 U1.M4(DIFFIO_RX_L24N)
OV5640_CLK24MHZ: J3.12 R211.2
OV5640_CLK24MHZ_R: R211.1 U14.18(CLK1A)
OV5640_CLK_HS_N: J3.5 R97.1 R102.1 U1.V9(DIFFIO_TX_RX_B18N/CLK6N)
OV5640_CLK_HS_P: J3.6 R95.1 R96.2 U1.V10(DIFFIO_TX_RX_B18P/CLK6P)
OV5640_CLK_LP_N: R102.2 U1.R14(DIFFIO_RX_R25N/DQ1R)
OV5640_CLK_LP_P: R95.2 U1.R15(DIFFIO_RX_R25P/DQ1R)
OV5640_DATA_HS_N1: J3.8 R105.1 R106.1 U1.AB12(DIFFIO_RX_B29N)
OV5640_DATA_HS_N2: J3.1 R109.1 R110.1 U1.AB10(DIFFIO_RX_B27N)
OV5640_DATA_HS_P1: J3.9 R103.1 R104.2 U1.AB13(DIFFIO_RX_B29P)
OV5640_DATA_HS_P2: J3.2 R107.1 R108.2 U1.AB11(DIFFIO_RX_B27P)
OV5640_DATA_LP_N1: R106.2 U1.W20(DIFFIO_RX_R21N)
OV5640_DATA_LP_N2: R110.2 U1.P14(DIFFIO_RX_R30N/DQ1R)
OV5640_DATA_LP_P1: R103.2 U1.W19(DIFFIO_RX_R21P)
OV5640_DATA_LP_P2: R107.2 U1.P15(DIFFIO_RX_R30P/DQ1R)
OV5640_SDA: J3.14 R100.2 U1.L1(DIFFIO_RX_L25P)
OV5640_SDC: J3.13 R101.2 U1.M3(DIFFIO_RX_L24P)
OV10640_24MHZ: R94.2 U1.N5(DIFFIO_RX_L28P/CLK0P)
OV10640_24MHZ_IO: J2.26 R94.1
OV10640_CLK_HS_N: J2.12 R75.1 R77.1 U1.R11(DIFFIO_TX_RX_B20N/CLK7N)
OV10640_CLK_HS_P: J2.11 R71.1 R73.2 U1.P11(DIFFIO_TX_RX_B20P/CLK7P)
OV10640_CLK_LP_N: R77.2 TP68.1(TP) U1.T22(DIFFIO_RX_R26N)
OV10640_CLK_LP_P: R71.2 TP67.1(TP) U1.T21(DIFFIO_RX_R26P)
OV10640_CMOS_RST: C36.1 J2.23 R91.2 U1.P4(DIFFIO_RX_L29N)
OV10640_CMOS_SCLK: J2.25 R92.2 U1.P5(DIFFIO_RX_L29P)
OV10640_CMOS_SDATA: J2.24 R89.2 U1.N8(DIFFIO_RX_L41N)
OV10640_DATA_HS_N1: J2.9 R83.1 R86.1 U1.AB21(DIFFIO_RX_B50N)
OV10640_DATA_HS_N2: J2.15 R90.1 R93.1 U1.AB19(DIFFIO_RX_B44N)
OV10640_DATA_HS_N3: J2.18 R76.1 R78.1 U1.AB17(DIFFIO_RX_B58N)
OV10640_DATA_HS_N4: J2.21 R84.1 R85.1 U1.AB16(DIFFIO_RX_B42N)
OV10640_DATA_HS_P1: J2.8 R79.1 R81.2 U1.AA20(DIFFIO_RX_B50P)
OV10640_DATA_HS_P2: J2.14 R87.1 R88.2 U1.AB20(DIFFIO_RX_B44P)
OV10640_DATA_HS_P3: J2.17 R72.1 R74.2 U1.AB18(DIFFIO_RX_B58P)
OV10640_DATA_HS_P4: J2.20 R80.1 R82.2 U1.AA16(DIFFIO_RX_B42P)
OV10640_DATA_LP_N1: R86.2 TP48.1(TP) U1.N22(DIFFIO_RX_R31N)
OV10640_DATA_LP_N2: R93.2 TP54.1(TP) U1.V22(DIFFIO_RX_R24N)
OV10640_DATA_LP_N3: R78.2 TP60.1(TP) U1.W22(DIFFIO_RX_R20N)
OV10640_DATA_LP_N4: R85.2 TP66.1(TP) U1.AA22(DIFFIO_RX_R2N)
OV10640_DATA_LP_P1: R79.2 TP45.1(TP) U1.P21(DIFFIO_RX_R31P)
OV10640_DATA_LP_P2: R87.2 TP50.1(TP) U1.V21(DIFFIO_RX_R24P)
OV10640_DATA_LP_P3: R72.2 TP57.1(TP) U1.Y22(DIFFIO_RX_R20P)
OV10640_DATA_LP_P4: R80.2 TP63.1(TP) U1.AA21(DIFFIO_RX_R2P)
OV10640_FSIN: J2.32 U1.P8(DIFFIO_RX_L47N)
OV10640_G_RDY: J2.28 U1.R4(DIFFIO_RX_L39N)
OV10640_GYRO_INT: J2.27 U1.N9(DIFFIO_RX_L41P)
OV10640_XM_INT1: J2.31 U1.R7(DIFFIO_RX_L47P)
OV10640_XM_INT2: J2.30 U1.R5(DIFFIO_RX_L39P)
PMODA_D0: R156.1 U1.A6(DIFFIO_RX_T41N)
PMODA_D1: R157.1 U1.E8(DIFFIO_RX_T48P)
PMODA_D2: R160.1 U1.B4(DIFFIO_RX_T46N)
PMODA_D3: R163.1 U1.A5(DIFFIO_RX_T43P)
PMODA_D4: R158.2 U1.B7(DIFFIO_RX_T41P)
PMODA_D5: R159.2 U1.E9(DIFFIO_RX_T44N)
PMODA_D6: R161.2 U1.A4(DIFFIO_RX_T43N)
PMODA_D7: R164.2 U1.B5(DIFFIO_RX_T47P)
PMODA_IO0: J8.1 R156.2 U9.3(IO2)
PMODA_IO1: J8.2 R157.2 U9.4(IO3)
PMODA_IO2: J8.3 R160.2 U8.6(IO4)
PMODA_IO3: J8.4 R163.2 U8.1(IO1)
PMODA_IO4: J8.7 R158.1 U9.1(IO1)
PMODA_IO5: J8.8 R159.1 U9.6(IO4)
PMODA_IO6: J8.9 R161.1 U8.4(IO3)
PMODA_IO7: J8.10 R164.1 U8.3(IO2)
PMODB_D0: R171.1 U1.C8(DIFFIO_RX_T39P)
PMODB_D1: R173.1 U1.D8(DIFFIO_RX_T42P)
PMODB_D2: R175.1 U1.A3(DIFFIO_RX_T45N)
PMODB_D3: R177.1 U1.A2(DIFFIO_RX_T45P)
PMODB_D4: R172.2 U1.B3(DIFFIO_RX_T46P)
PMODB_D5: R174.2 U1.C2(DIFFIO_RX_T53N)
PMODB_D6: R176.2 U1.B1(DIFFIO_RX_T51N)
PMODB_D7: R178.2 U1.B2(DIFFIO_RX_T51P)
PMODB_IO0: J9.1 R171.2 U10.1(IO1)
PMODB_IO1: J9.2 R173.2 U10.3(IO2)
PMODB_IO2: J9.3 R175.2 U10.6(IO4)
PMODB_IO3: J9.4 R177.2 U11.6(IO4)
PMODB_IO4: J9.7 R172.1 U10.4(IO3)
PMODB_IO5: J9.8 R174.1 U11.3(IO2)
PMODB_IO6: J9.9 R176.1 U11.1(IO1)
PMODB_IO7: J9.10 R178.1 U11.4(IO3)
SI5338_INTR: R205.1 U4.A1(IOB2_1) U14.8(INTR)
SI5338A_XTAL_25M_N: C89.2 U14.2(CLKIN_N) Y2.1
SI5338A_XTAL_25M_P: C87.2 U14.1(CLKIN_P) Y2.3
TMDS_CLK_N: D1.1 J4.12(TMDS_CLK_N) U3.17(TXC-)
TMDS_CLK_P: D1.2 J4.10(TMDS_CLK_P) U3.18(TXC+)
TMDS_DATA_N0: D1.3 J4.9(TMDS_DATA_N0) U3.20(TX0-)
TMDS_DATA_N1: D2.1 J4.6(TMDS_DATA_N1) U3.23(TX1-)
TMDS_DATA_N2: D2.3 J4.3(TMDS_DATA_N2) U3.26(TX2-)
TMDS_DATA_P0: D1.4 J4.7(TMDS_DATA_P0) U3.21(TX0+)
TMDS_DATA_P1: D2.2 J4.4(TMDS_DATA_P1) U3.24(TX1+)
TMDS_DATA_P2: D2.4 J4.1(TMDS_DATA_P2) U3.27(TX2+)
USB_ADDR0: U1.E1(DIFFIO_RX_L21N) U4.R20(IOB3_40)
USB_ADDR1: U1.G3(DIFFIO_RX_L6P/ADC2IN6) U4.J20(IOB3_25)
USB_CLK: U1.E11(DIFFIO_RX_T38P/CLK4P) U4.K1(IOB1/GCLK0) U7.13(IFCLK)
USB_DATA0: U1.H4(DIFFIO_RX_L6N/ADC2IN5) U4.H20(IOB3_23)
USB_DATA1: U1.F1(DIFFIO_RX_L23P) U4.T20(IOB3_44)
USB_DATA2: U1.E4(DIFFIO_RX_L2N/ADC2IN1) U4.E20(IOB3_12)
USB_DATA3: U1.E3(DIFFIO_RX_L2P/ADC2IN8) U4.P20(IOB3_36)
USB_DATA4: U1.G1(DIFFIO_RX_L23N) U4.V20(IOB3_50)
USB_DATA5: U1.H1(DIFFIO_RX_L22N) U4.W20(IOB3_52)
USB_DATA6: U1.H3(DIFFIO_RX_L5P/ADC1IN6) U4.K20(IOB3_27)
USB_DATA7: U1.J3(DIFFIO_RX_L8P/ADC2IN2) U4.Y20(IOB3_53)
USB_DISABLEN: J7.2 R147.2 U4.E17(IOB3_9)
USB_EMPTY: R138.2 U1.F3(DIFFIO_RX_L4P/ADC2IN4) U4.G20(IOB3_20)
USB_FULL: R142.2 U1.F4(DIFFIO_RX_L1P/ADC1IN2) U4.F20(IOB3_16)
USB_OEN: U1.F2(DIFFIO_RX_L21P) U4.U20(IOB3_48)
USB_RDN: U1.J4(DIFFIO_RX_L5N/ADC1IN5) U4.L20(IOB3/GCLK3)
USB_RESETN: U1.K2(DIFFIO_RX_L19N) U4.Y18(IOB4_42)
USB_SCL: R140.2 U1.D2(DIFFIO_RX_L16P) U4.D20(IOB3_8)
USB_SDA: R141.2 U1.D3(DIFFIO_RX_L16N) U4.C20(IOB3_4)
USB_WRN: U1.J1(DIFFIO_RX_L22P) U4.Y19(IOB4_43)
USER_CLKIN_IO_N: J12.5 R268.1
USER_CLKIN_IO_P: J12.3 R179.1
USER_CLKIN_N_MAX10: R268.2 R269.2 R272.1 U1.K21(DIFFIO_RX_R40N/CLK3N)
USER_CLKIN_P: R179.2 R180.2 R271.1 R272.2
USER_CLKIN_P_MAX10: R270.2 R271.2 U1.K22(DIFFIO_RX_R40P/CLK3P)
USER_DIPSW0: R181.2 SW1.8(B1) U1.R18(DIFFIO_RX_R32P/DQS1R)
USER_DIPSW1: R182.2 SW1.7(B2) U1.T19(DIFFIO_RX_R27P/DQ1R)
USER_DIPSW2: R184.2 SW1.6(B3) U1.T18(DIFFIO_RX_R27N/DM1R)
USER_DIPSW3: R185.2 SW1.5(B4) U1.U19(DIFFIO_RX_R19N)
USER_DIPSW4: R189.2 SW2.8(B1) U1.G4(DIFFIO_RX_L4N/ADC2IN3)
USER_DIPSW5: R190.2 SW2.7(B2) U1.F5(DIFFIO_RX_L1N/ADC1IN1)
USER_IO0: J14.1(IO1) U1.A17(DIFFIO_RX_T10N)
USER_IO1: J14.3(IO3) U1.B19(DIFFIO_RX_T6N)
USER_IO2: J14.7(IO7) U1.E16(DIFFIO_RX_T1P)
USER_IO3: J14.9(IO9) U1.C19(DIFFIO_RX_T6P)
USER_IO4: J14.13(IO13) U1.F16(DIFFIO_RX_T5P)
USER_IO5: J14.2(IO2) U1.A19(DIFFIO_RX_T8N)
USER_IO6: J14.4(IO4) U1.A20(DIFFIO_RX_T8P)
USER_IO7: J14.8(IO8) U1.C18(DIFFIO_RX_T7P)
USER_IO8: J14.10(IO10) U1.C17(DIFFIO_RX_T2N)
USER_IO9: J14.14(IO14) U1.D17(DIFFIO_RX_T2P)
USER_LED0: D3.2(CATHODE) U1.C3(DIFFIO_RX_T53P)
USER_LED0_R: D3.1(ANODE) R183.2
USER_LED1: D4.2(CATHODE) U1.C4(DIFFIO_RX_T47N)
USER_LED1_R: D4.1(ANODE) R186.2
USER_LED2: D5.2(CATHODE) U1.C5(DIFFIO_RX_T49P)
USER_LED2_R: D5.1(ANODE) R187.2
USER_LED3: D6.2(CATHODE) U1.D5(DIFFIO_RX_T49N)
USER_LED3_R: D6.1(ANODE) R188.2
USER_LED4: D7.2(CATHODE) U1.C7(DIFFIO_RX_T39N)
USER_LED4_R: D7.1(ANODE) R193.2
USER_LVDS_N0: J12.11 R153.1 U1.Y10(DIFFIO_TX_RX_B22N)
USER_LVDS_N1: J12.17 R154.1 U1.W7(DIFFIO_TX_RX_B13N)
USER_LVDS_N2: J12.6 R155.1 U1.AA17(DIFFIO_TX_RX_B43N)
USER_LVDS_N3: J12.12 R162.1 U1.Y13(DIFFIO_TX_RX_B37N)
USER_LVDS_N4: J13.12 R165.1 U1.W9(DIFFIO_TX_RX_B11N)
USER_LVDS_N5: J13.5 R166.1 U1.V7(DIFFIO_TX_RX_B7N)
USER_LVDS_N6: J13.11 R167.1 U1.W5(DIFFIO_TX_RX_B1N)
USER_LVDS_N7: J13.17 R168.1 U1.W4(DIFFIO_TX_RX_B5N)
USER_LVDS_N8: J13.6 R169.1 U1.AA6(DIFFIO_TX_RX_B16N)
USER_LVDS_P0: J12.9 R153.2 U1.AA10(DIFFIO_TX_RX_B22P)
USER_LVDS_P1: J12.15 R154.2 U1.W8(DIFFIO_TX_RX_B13P)
USER_LVDS_P2: J12.4 R155.2 U1.Y17(DIFFIO_TX_RX_B43P)
USER_LVDS_P3: J12.10 R162.2 U1.Y14(DIFFIO_TX_RX_B37P)
USER_LVDS_P4: J13.10 R165.2 U1.W10(DIFFIO_TX_RX_B11P)
USER_LVDS_P5: J13.3 R166.2 U1.V8(DIFFIO_TX_RX_B7P)
USER_LVDS_P6: J13.9 R167.2 U1.W6(DIFFIO_TX_RX_B1P)
USER_LVDS_P7: J13.15 R168.2 U1.W3(DIFFIO_TX_RX_B5P)
USER_LVDS_P8: J13.4 R169.2 U1.AA7(DIFFIO_TX_RX_B16P)
USER_PB0: R202.2 S1.3 S1.4 U1.R20(DIFFIO_RX_R28N/DQ1R)
USER_PB1: R196.2 S2.3 S2.4 U1.Y20(DIFFIO_RX_R22P)
USER_PB2: R195.2 S3.3 S3.4 U1.Y21(DIFFIO_RX_R22N)
USER_PB3: R198.2 S4.3 S4.4 U1.U20(DIFFIO_RX_R23N)
VREF_1V2HSTL: C4.2 C8.1 R9.1 R11.2 U1.P22(VREFB5N0)
VREF_1V8HSTL: C1.1 C3.1 R1.1 R2.2 U1.M2(VREFB2N0)
VREF_LPDDR2: C6.2 C9.1 R10.1 R12.2 U1.D21(VREFB6N0)
N31901: R118.1 R119.2 U3.22(PD)
N16765826: J5.4(ID) R124.1
N16772990: C71.1 R143.2
N16895577: R206.2 U14.12(SCL)
N16895579: R209.2 U14.19(SDA)
N16938690: R217.2 SW3.2(NC1) SW3.5(NC2)
N16938718: R221.2 R264.1 SW3.3(COMMON1) SW3.4(COMMON2)
N16938802: C97.1 U18.5(TIMER)
N16938806: C99.1 U18.6(INTVCC)
N16938884: C98.2 R231.1
N16939009: R225.1 U16.4(G)
N16939055: R222.1 U16.5(D) V2.2(SNS)
N16993273: C105.2 R235.2 U20.5(VSENSE)
N17581797: C216.1 R290.1 R291.2 U19.4(VFB)
N17604176: C31.1 R73.1 R75.2
N17604218: C33.1 R81.1 R83.2
N17604268: C35.1 R88.1 R90.2
N17605267: C32.1 R74.1 R76.2
N17605327: C34.1 R82.1 R84.2
N17606282: C37.1 R96.1 R97.2
N17606316: C40.1 R104.1 R105.2
N17606350: C41.1 R108.1 R109.2

Pads without a net: D1 6; J1 1 2; J2 35 36; J4 13 14; J6 6 7 8; J7 6 8; J13 16 18; NOREF 1; NOREF#2 1; NOREF#8 1; NOREF#10 1; NOREF#12 1; NOREF#14 1; NOREF#15 1; NOREF#16 1; NOREF#17 1; NOREF#18 1; NOREF#19 1; NOREF#20 1; U1 A15 AA1 AA2 AA3 AA8 AA9 AA11 AA12 AA13 AA14 AA15 AA19 AB4 AB8 AB9 AB14 AB15 B15 C1 C6 D1 D7 D10 F7 K8 L3 L8 L9 M1 P9 P10 P12 P13 R9 R10 R12 R13 U6 U7 U15 V11 V12 V13 V14 V15 V16 W11 W12 W13 W14 W15 W16 W18 Y3 Y4 Y5 Y6 Y7 Y8 Y11 Y16 Y18 Y19; U2 A1 A2 A9 A10 B1 B2 B3 B7 B8 B9 B10 C3 C8 D6 D7 D8 D9 E5 E6 E7 J2 K2 K3 L2 L3 N5 N6 N7 P6 P7 P8 P9 R3 R8 T1 T2 T3 T7 T8 T9 T10 U1 U2 U9 U10; U3 3 4 5 6 7 8 9 10; U4 A2 A3 A4 A5 A8 A9 A10 A11 A17 A18 A19 A20 B2 B3 B4 B5 B6 B7 B8 B9 B10 B11 B12 B13 B14 B15 B16 B17 B18 B19 C2 C3 C4 C5 C6 C7 C14 C15 C16 C17 C18 C19 D2 D3 D5 D6 D7 D8 D13 D14 D15 D16 D17 D18 D19 E2 E3 E18 E19 F2 F3 F18 F19 G2 G3 G18 G19 H2 H19 J2 J19 K2 K19 L2 L19 M2 M19 N2 N17 N19 N20 P2 P3 P17 P18 P19 R2 R3 R17 R18 R19 T1 T2 T17 T18 T19 U1 U3 U4 U5 U6 U7 U8 U15 U17 U18 U19 V1 V3 V4 V5 V6 V7 V14 V15 V16 V17 V18 V19 W1 W3 W4 W5 W6 W7 W8 W9 W10 W11 W12 W13 W14 W15 W16 W17 W18 W19 Y1 Y12 Y14 Y15 Y16; U5 3; U7 54; U14 5 14 17; U15 1; U17 1 13 21 22 23 24; U18 1 14; U19 1 3 8 9 13 14; U20 1 4 15 16; U21 1 13 21 22 23 24; U22 1 3 8 9 13 14; U23 4 5 6 11 12 13 14

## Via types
v1: diameter 0.406, hole 0.203, TOP to BOTTOM, 467 vias
v2: diameter 0.559, hole 0.254, TOP to BOTTOM, 503 vias
v3: diameter 0.356, hole 0.203, TOP to BOTTOM, 148 vias
v4: diameter 0.61, hole 0.305, TOP to BOTTOM, 184 vias
v5: diameter 0.635, hole 0.33, TOP to BOTTOM, 68 vias

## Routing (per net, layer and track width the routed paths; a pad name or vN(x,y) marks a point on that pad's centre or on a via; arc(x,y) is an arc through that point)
1.2V_CORE: length 17
  TOP w0.381: U1.M11 v1(55.51,36.46) ; U1.N12 v1(57.52,35.46) ; U1.M12 v1(56.52,36.46) ; U1.J7 v1(52.52,39.46) ; U1.L11 56.02,37.97 v1(56.51,38.46) ; U1.L12 v1(57.52,38.47) ; U1.K13 v1(58.52,39.47) ; U1.K11 v1(55.51,38.47) ; U1.L10 v1(54.51,38.47)
  TOP w0.406: U1.M13 v1(57.52,36.46) ; U1.N10 v1(54.51,35.46)
  BOTTOM w0.381: v1(54.51,38.47) 54.04,37.99 C222.1 ; v1(57.52,35.46) 57.01,34.96 C221.1 ; C226.2 56.91,37.96 56.51,38.37 v1(56.51,38.46) ; C231.2 58.01,38.96 v1(57.52,38.47) ; C223.1 52.32,40.08 52.52,39.88 v1(52.52,39.46) ; C230.2 59.01,39.87 58.61,39.47 v1(58.52,39.47) ; C227.2 56.02,38.87 55.62,38.47 v1(55.51,38.47) ; v1(57.52,36.46) 57.42,36.46 57.01,36.06 C229.2 ; C224.2 56.11,36.97 56.52,36.57 v1(56.52,36.46) ; C228.2 v1(55.51,36.46) ; C225.2 54.01,35.07 54.41,35.46 v1(54.51,35.46)
  vias: v2(41.66,37.08) v2(42.42,37.08) v2(43.18,37.08) v4(22.48,34.29) v4(22.48,33.53) v4(22.48,32.77) v4(23.37,34.29) v4(23.37,33.53) v4(23.37,32.77)
1.2V_CORE_ENABLE: length 4
  TOP w0.305: U21.18 20.04,27.58 v2(20.19,27.43)
  BOTTOM w0.406: C174.1 20.07,27.3 v2(20.19,27.43) 20.32,27.3 R252.1 R283.1
1.2V_CORE_POK: length 26.9
  TOP w0.305: v2(31.5,36.32) 31.5,40.09 32,40.59 U4.Y11 ; v2(20.19,26.54) 19.8,26.93 19.15,26.93 U21.17
  ART04 w0.406: v2(20.19,26.54) 29.34,26.54 30.35,27.56 30.35,35.18 v2(31.5,36.32)
  BOTTOM w0.406: R239.1 19.94,26.29 v2(20.19,26.54)
1.2V_CORE_SENSE: length 9.7
  TOP w0.406: C112.2 R240.2 10.41,26.03 9.53,26.92 9.53,30.48 9.84,30.8 C114.1
  vias: v4(10.54,33.4) v4(10.54,32.64) v4(10.54,31.88) v4(11.3,33.4) v4(11.3,32.64) v4(11.3,31.88)
1.2V_CORE_VFB: length 6
  TOP w0.305: U21.14 16.82,25.52 16.44,25.15 15.05,25.15 14.8,24.89 R243.2 arc(14.79,24.49) 14.76,24.48
  TOP w0.406: 14.76,24.48 14.38,24.48 14.1,24.77 C112.1 R240.1
1.2V_LED: length 4.1
  TOP w0.147: U4.Y9 31,40.67 30.73,40.4 30.73,39.45 29.06,37.77 D11.2
1.2V_LED_R: length 1.3
  TOP w0.147: R278.2 D11.1
1.2V_VCCD_PLL: length 37.3
  TOP w0.381: U1.T7 v1(52.51,32.46) ; U1.G16 v1(61.52,42.47) ; U1.U16 v1(61.52,31.46) ; U1.G7 v1(51.51,42.47)
  TOP w0.508: v2(37.59,37.97) v2(37.59,37.21) C122.1
  ART04 w0.305: 58.99,37.46 58.99,40.7 59.28,41 59.71,41 59.99,41.27 59.99,41.6 60.32,41.94 60.99,41.94 v1(61.52,42.47) ; 57.02,39.88 57.02,40.89 55.92,42 54.25,42 53.98,42.27 53.98,42.27 53.98,42.66 53.98,42.67 53.98,42.68 53.72,42.94 52.21,42.94 51.74,42.47 v1(51.51,42.47) ; 57.78,34.93 60.71,34.93 60.99,34.66 60.99,31.99 v1(61.52,31.46)
  BOTTOM w0.305: v1(61.52,31.46) 61.42,31.46 61.01,31.87 C148.2 53.01,31.97 v1(52.51,32.46) C145.2
  BOTTOM w0.381: C146.2 v1(51.51,42.47) ; v1(61.52,42.47) 61.52,42.57 61.91,42.97 C147.2
1.2V_VCCIO: length 85.8
  TOP w0.305: U2.C10 v3(84.53,46.13) ; U2.H1 v3(78.03,42.23) ; U2.J6 v3(81.93,42.23) ; U2.T5 81.04,37.27 v3(81.28,37.04) ; U2.R7 v3(82.58,37.69) ; U2.K6 v3(81.28,40.94) ; U2.R10 v3(84.8,38.01) ; U2.F1 v3(77.78,43.86) ; U2.P5 v3(80.63,38.34) ; U2.H6 v3(81.28,42.88) ; U2.F10 v3(83.88,43.53) ; U2.D2 v3(78.68,45.48) ; U2.N9 83.64,39.22 v3(83.88,38.99) ; U2.N2 v3(78.68,38.99) ; v3(82.58,42.23) U2.J7 ; U2.D5 v3(81.28,45.48) ; U2.M10 v3(84.8,39.96) ; U2.P2 v3(79.33,38.99) ; U2.G1 v3(77.78,43.21) ; U2.B5 v3(81.28,46.78) ; U2.C7 v3(82.58,46.13) ; U2.E9 v3(83.88,44.83)
  TOP w0.381: U1.T17 v1(62.52,33.46) ; U1.M17 v1(62.52,36.46) ; U1.J17 v1(62.52,40.47) ; U1.R16 v1(61.52,33.46) ; U1.K17 v1(62.52,39.47) ; U1.K16 v1(61.52,39.47) ; U1.H16 v1(61.52,41.47) ; U1.N17 v1(61.52,35.46) ; v1(60.51,35.47) 61.01,35.96 U1.N16 ; U1.R17 v1(62.52,34.46) ; U1.L16 v1(61.52,38.47) ; U1.P16 v1(61.52,34.46)
  TOP w0.406: C208.2 R285.2 v2(83.95,51.18)
  BOTTOM w0.203: U22.7 86.7,52.27 85.78,52.27 ; U22.6 86.7,51.87 85.78,51.87
  BOTTOM w0.305: v3(81.28,42.88) 81.18,42.99 C17.1 ; C19.1 78.61,45.42 v3(78.68,45.48) ; v3(82.58,42.23) 82.74,42.07 C22.1 ; C14.1 85.03,37.78 v3(84.8,38.01) ; v3(82.58,37.69) 83.09,37.69 83.25,37.85 C16.1 v3(83.88,38.99) ; v3(81.28,40.94) 81.51,40.7 C25.1 ; C21.1 82.74,45.97 v3(82.58,46.13) ; v3(77.78,43.21) 77.94,43.05 C23.1 ; C245.1 83.94,44.89 v3(83.88,44.83) ; v3(84.53,46.13) 84.39,46.27 C244.1 ; v3(81.28,46.78) 81.66,47.17 C18.1 ; v3(80.63,38.34) 80.84,38.54 C20.1 ; v3(77.78,43.86) 77.76,43.88 C246.1
  BOTTOM w0.381: v1(61.52,38.47) 61.52,37.68 C234.2 ; C233.2 v1(61.52,41.47) ; v1(62.52,36.46) 62.02,35.97 C194.1 ; v1(62.52,39.47) 62.61,39.47 63.01,39.06 C236.2 ; v1(62.52,40.47) 62.62,40.47 63.01,40.07 C235.2 ; v3(84.8,39.96) 84.88,39.96 85.28,39.56 C15.1 ; C149.2 v1(60.51,35.47)
  BOTTOM w0.406: v2(69.6,37.62) 69.98,37.24 C4.1 R9.2 ; v2(68.83,33.15) R7.1 ; C241.1 R29.2 80.71,49.72 v2(80.64,49.78) ; 86.74,47.12 85.34,47.12 83.95,48.51 v2(83.95,51.18)
  BOTTOM w0.508: 88.01,24.89 88.01,21.21 86.74,19.94 R196.1 84.26,16.83 81.92,14.48 78.11,14.48 77.22,13.59 69.22,13.59 67.63,15.18 R198.1 R195.1
  vias: v2(70.48,47.24) v2(71.37,47.24) v2(88.27,32.38) v2(88.27,31.12) v2(88.27,29.84) v2(88.27,28.58) v4(86.23,43.81) v4(86.23,43.05) v4(87,43.81) v4(87,43.05) v4(87.76,43.81) v4(87.76,43.05)
1.2V_VCCIO_ENABLE: length 3.6
  TOP w0.406: v2(87.38,53.85) R241.1 C119.1 R242.1
  BOTTOM w0.203: U22.10 87.63,53.59 v2(87.38,53.85)
1.2V_VCCIO_VFB: length 3.6
  TOP w0.406: v2(87.12,50.42) 87.12,50.74 R285.1 C208.1 R286.2
  BOTTOM w0.203: v2(87.12,50.42) 87.23,50.53 U22.4
1.8V: length 99.7
  TOP w0.305: 81.93,47.88 v3(81.93,46.78) U2.B6 ; 77.72,37.38 v3(78.03,37.69) U2.R1 ; 77.72,46.44 v3(78.03,46.13) U2.C1 ; U2.T6 81.69,37.27 v3(81.93,37.04) 81.93,35.94
  TOP w0.381: U1.N7 v1(51.51,35.46) ; U1.R6 v1(50.51,33.46) ; U1.P7 v1(51.51,34.46) ; U1.N6 v1(50.51,35.46)
  TOP w0.406: v4(83.82,25.78) 83.06,25.78 82.55,25.27 82.55,23.24 83.06,22.73 v4(83.69,22.73) ; v2(80.77,56.52) 83.44,53.85 R241.2
  TOP w0.508: 77.72,46.44 77.72,47.5 ; v4(13.97,54.23) v4(13.97,54.99) 14.03,54.93 L6.2
  TOP w0.635: 81.93,35.94 78.11,35.94 77.72,36.32 77.72,37.38
  TOP w0.762: 77.72,47.5 78.11,47.88 v4(91.19,47.88) v4(91.19,46.86) ; 81.93,35.94 83.07,34.8 89.79,34.8 v4(90.93,35.94) v4(90.93,36.83)
  ART04 w0.109: v4(83.82,25.78) 82.42,25.78 76.96,20.32 72.26,20.32 v2(72.01,20.57)
  BOTTOM w0.147: R305.1 27.75,18.48 27.94,18.29 v4(28.45,18.29)
  BOTTOM w0.203: U20.7 55.95,65.6 ; U20.8 55.93,65.21
  BOTTOM w0.305: v3(81.93,46.78) 81.94,46.8 C26.1 ; v3(81.93,37.04) 81.98,37.08 C247.1 ; v3(78.03,46.13) 77.91,46.25 C27.1 ; C243.1 77.81,37.91 v3(78.03,37.69)
  BOTTOM w0.381: R279.2 20.83,62.23 20.45,62.61 13.97,62.61 12.32,60.96 v4(9.91,60.96)
  BOTTOM w0.406: R91.1 v4(83.82,25.78) 85.6,27.56 85.6,29.34 ; R308.1 R68.1 39.94,19.62 v2(40.01,19.56) ; R92.1 84.26,22.42 83.95,22.73 v4(83.69,22.73) ; R89.1 72.39,20.19 v2(72.01,20.57)
  vias: v4(8.38,60.96) v4(8.38,60.2) v4(9.14,60.96) v4(9.14,60.2) v4(9.91,60.2) v4(26.8,28.58) v4(26.8,27.81) v4(27.56,28.58) v4(27.56,27.81) v4(56.01,72.64) v4(56.01,71.88) v4(56.77,72.64) v4(56.77,71.88) v4(56.77,71.12)
1.8V_AVDD: length 6.4
  TOP w0.254: v2(70.36,57.28) 70.23,57.28 69.92,56.97 U3.15 ; U3.19 71.04,58.84 v2(70.87,58.67) ; U3.25 71.5,61.84 v2(70.87,61.21)
  BOTTOM w0.406: C54.1 v2(70.87,58.67) ; C55.1 v2(70.87,61.21)
1.8V_DVDD: length 10.2
  TOP w0.254: v2(70.87,65.28) 71.3,64.84 U3.31 ; U3.11 67.92,57.04 v2(67.69,57.28) ; v2(62.74,57.4) 62.92,57.21 U3.1 ; U3.51 62.02,64.35 62.48,63.88 v2(62.48,63.12)
  BOTTOM w0.406: v2(67.69,57.28) 67.82,57.4 C47.1 ; C46.1 v2(62.48,63.12) ; C45.1 v2(62.74,57.4) ; C48.1 v2(70.87,65.28)
  vias: v2(62.23,56.77) v2(62.23,56.01) v2(62.23,55.24)
1.8V_ENABLE: length 3.8
  TOP w0.406: v2(53.72,63.37) C176.1 53.09,64.96 53.02,64.9 R257.2
  BOTTOM w0.203: v2(53.72,63.37) 53.78,63.43 U20.12
1.8V_PVDD: length 3
  TOP w0.254: v2(69.34,57.28) 68.92,56.86 U3.13 ; U3.12 68.43,57.12 v2(68.58,57.28)
1.8V_SI5338: length 3.1
  TOP w0.508: v2(16.76,54.36) 16.44,54.04 C88.1 L6.1
  BOTTOM w0.254: v2(16.76,54.36) 16.9,54.49 U14.20
2.5V: length 53.4
  TOP w0.203: 29.65,55.68 29.65,56.61 U19.6 ; 30.04,55.68 U19.7
  TOP w0.305: v3(34.04,45.34) 34.17,45.47 U4.L17 ; U4.D11 32,48.33 32.26,48.07 v3(32.26,48.01) ; U4.D11 U4.D10 ; U4.D11 U4.C11 U4.C10 ; v3(29.46,45.97) 29.03,45.97 29.03,45.97 U4.K4 ; U4.U11 32,43.18 v3(32.13,43.31) ; U4.D10 31.5,48.39 v3(31.11,48.01) ; U4.D10 U4.C10 ; U4.C10 U4.C9
  TOP w0.381: U1.T13 v1(57.52,33.46) ; U1.U9 v1(54.51,32.46) ; U1.U8 v1(53.51,32.46) ; U1.T10 v1(55.51,32.46) ; U1.T9 v1(54.52,33.47) ; C251.1 25.27,56.01 v4(25.4,55.88) ; U1.U12 v1(57.52,31.46) ; U1.T12 v1(57.52,32.46) ; U1.T11 v1(56.52,32.46) ; U1.U11 v1(55.51,31.46) ; U1.U14 v1(58.52,32.46)
  VCC03 w0.508: J12.1 85.08,10.16 ; J12.1 84.2,9.28 ; J12.1 83.32,10.16 ; J12.1 84.2,11.04 ; 41.53,9.28 J13.1 ; J13.1 40.65,10.16 ; J13.1 41.53,11.04 ; J13.1 42.41,10.16 ; J13.2 42.41,7.62 ; J13.2 40.65,7.62 ; J13.2 41.53,8.5 ; J12.2 85.08,7.62 ; J12.2 83.32,7.62 ; J12.2 84.2,8.5
  BOTTOM w0.305: C77.1 32.19,43.24 v3(32.13,43.31) ; C73.1 34.23,45.15 v3(34.04,45.34) ; v3(32.26,48.01) 32.26,47.43 C76.1 ; v3(31.11,48.01) 31.11,48.51 30.86,48.77 C72.1 R139.1 R137.1
  BOTTOM w0.381: R200.2 29.27,53.72 27.81,53.72 27.27,54.26 27.27,54.83 ; v1(57.52,31.46) 57.41,31.46 57.01,31.07 C144.2 ; v1(55.51,31.46) 55.62,31.46 56.02,31.07 C239.2 ; 28.07,54.74 28.38,54.42 R290.2 C216.2
  BOTTOM w0.406: R205.2 25.21,55.94 ; v2(37.97,42.16) 37.97,39.75 38.48,39.24 41.4,39.24 41.78,39.62 R25.1 ; R283.2 21.91,25.72 v2(21.59,25.4) ; R24.1 v2(41.47,42.16) ; R21.1 v2(39.62,42.16)
  vias: v2(38.73,49.78) v2(38.73,49.02) v2(39.5,49.78) v2(39.5,49.02) v4(25.4,54.99) v4(26.16,54.99) v4(26.92,54.99)
2.5V_ENABLE: length 6
  TOP w0.203: U19.10 31.11,57.53 31.37,57.28 31.37,56.77 32,56.13 v2(32.83,56.13)
  BOTTOM w0.406: 32.83,56.18 32.56,56.45 R282.1 ; 32.83,56.18 v2(32.83,56.13) ; 32.83,56.18 C175.1 R255.1
2.5V_LED_R: length 2.1
  TOP w0.305: D10.1 v2(31.57,53.59)
  BOTTOM w0.381: R200.1 31.57,53.1 v2(31.57,53.59)
2.5V_VCCA: length 33
  TOP w0.381: U1.H8 v1(52.51,41.47) ; U1.H7 v1(51.51,41.47) ; U1.T15 v1(60.52,32.46) ; U1.R8 v1(53.51,33.46) ; U1.H15 v1(60.52,41.47)
  BOTTOM w0.305: R267.2 46.88,40.94 50.72,40.94 51.24,41.47 v1(51.51,41.47) v1(52.51,41.47) ; v1(60.52,41.47) 60.52,41.37 60.11,40.96 C206.2 60.01,40.97 57.28,40.97 57.01,40.7 57.01,40.25 56.73,39.97 54.02,39.97 C238.2 53.34,40.64 53.01,40.31 53.01,33.97 C124.2 53.02,33.96 v1(53.51,33.46) 53.51,33.46 54.01,32.97 C237.2 60.01,32.87 60.42,32.46 v1(60.52,32.46)
3.3V: length 169.2
  TOP w0.305: v3(31.24,44.2) v3(31.24,43.31) 31.5,43.05 U4.U10 U4.V10 U4.V11 U4.V12 ; v3(33.15,45.97) v3(34.04,45.97) 34.16,45.97 34.17,45.97 U4.K17 U4.K18 ; U4.L3 U4.K3 ; U4.L3 U4.M3 ; U4.L3 U4.L4 29.21,45.47 v3(29.46,45.21) v3(29.97,45.21) ; U4.K18 U4.J18 ; U4.K18 U4.L18
  TOP w0.381: v1(51.51,38.47) 51.52,38.47 U1.K7 v1(51.51,39.47) ; v1(51.51,38.47) U1.L7 51.31,37.26 U1.M6 ; v1(51.51,38.47) 51.51,38.46 U1.L6 v1(50.51,38.47) ; U1.G10 v1(54.51,42.47) ; U1.G11 v1(55.51,42.47) ; U1.F9 v1(53.51,43.47) ; v1(59.52,43.47) U1.F14 ; U1.G14 v1(59.52,42.47) ; U1.G12 v1(57.52,42.47) ; U1.G13 v1(58.52,42.47) ; U1.F11 v1(55.51,43.47) ; U1.F12 v1(57.52,43.47)
  TOP w0.406: v2(14.22,46.7) 14.89,46.7 C70.1 ; C65.1 v2(21.59,49.78) ; C69.1 22.73,40.51 v3(22.61,40.39) ; R192.1 R191.1 R190.1 R189.1 42.1,51.24 41.78,51.56 v2(41.78,52.83) ; C64.1 16.76,49.87 v2(16.8,49.91) ; C67.1 v2(14.22,44.7) ; C66.1 v2(14.22,42.67) ; v2(23.88,46.86) 23.81,46.8 C68.1
  TOP w0.508: R194.1 R278.1 28.32,33.97 27.56,34.73 27.56,34.75 27.43,34.87 v4(27.43,35.56) ; v4(27.81,19.94) 27.81,20.64 27.88,20.7 R204.1 ; v2(11.56,53.85) 10.99,53.28 R145.2 ; R146.2 10.99,48.45 v2(11.43,48.89) ; v4(25.65,62.99) 26.42,62.23 R281.2 ; R245.1 v2(49.28,57.28) R244.1 ; v2(49.28,52.45) C169.2 C170.1 v2(49.28,53.34) ; v2(10.03,53.98) 7.94,53.98 ; R147.1 v2(12.7,56.52) ; C63.1 16.07,40.2 v2(16.13,40.26)
  VCC03 w0.508: 63.5,72.72 J14.6 ; J14.6 62.56,73.66 ; J14.6 64.44,73.66 ; 46.99,65.48 J8.12 ; J8.12 46.99,67.36 ; J8.12 46.05,66.42 ; J8.12 47.93,66.42 ; 62.56,71.12 J14.5 ; J14.5 63.5,72.06 ; J14.5 63.5,70.18 ; J14.5 64.44,71.12 ; 23.19,66.42 J9.12 24.13,65.48 ; J8.6 47.93,63.88 ; J8.6 46.99,64.82 ; J8.6 46.05,63.88 ; J8.6 46.99,62.94 ; 23.19,63.88 J9.6 ; J9.6 24.13,64.82 ; J9.6 25.07,63.88 ; J9.6 24.13,62.94
  ART04 w0.406: 25.02,39.88 23.11,39.88 v3(22.61,40.39)
  ART04 w0.508: v4(23.75,23.11) 24.51,23.11 25.02,22.61 25.02,20.95 26.29,19.69 27.56,19.69 v4(27.81,19.94) 28.83,18.92 38.23,18.92 v2(38.35,18.8)
  BOTTOM w0.254: U7.17 v2(16.8,49.91) ; v3(22.61,40.39) 22.3,40.69 U7.43 ; v2(23.88,46.86) 23.85,46.84 U7.32 ; U7.7 14.36,44.84 v2(14.22,44.7) ; U7.3 14.39,42.84 v2(14.22,42.67) ; U7.11 14.36,46.84 v2(14.22,46.7) ; U7.55 16.3,40.43 v2(16.13,40.26) ; U7.27 21.8,49.57 v2(21.59,49.78)
  BOTTOM w0.305: C75.1 v3(31.24,44.2) ; v3(34.04,45.97) 34.1,46.04 C81.1 ; v3(29.46,45.21) 29.15,45.53 C79.1 ; v3(33.15,45.97) 32.96,46.16 C74.1 ; C80.1 31.18,43.24 v3(31.24,43.31) ; C78.1 30.04,45.21 v3(29.97,45.21)
  BOTTOM w0.381: C155.2 50.02,38.96 v1(50.51,38.47) C156.2
  BOTTOM w0.406: v1(55.51,42.47) 55.53,42.48 R203.1 ; R223.2 C91.1 32.32,67.12 33.78,68.58 35.31,68.58 36.07,69.34 36.07,72.14 35.81,72.39 C92.1 ; v2(38.35,18.8) 38.1,19.05 R303.1 ; L9.1 v2(44.2,53.98)
  BOTTOM w0.508: U5.4 28.83,41.1 28.82,41.08 C58.2 28.32,39.88 26.67,38.23 v4(26.67,37.21) ; R27.1 R28.1 50.29,49.78 v2(49.66,50.42) ; v4(41.15,52.32) R309.1 ; J6.4 v2(10.16,48.89) v2(11.43,48.89) ; R128.1 R127.1 25.72,51.75 v2(25.27,51.31) ; v2(2.79,64.64) v2(2.03,64.64) 1.97,64.58 R193.1 R188.1 R187.1 R186.1 R183.1 ; U10.5 10.41,68.71 v2(10.67,68.45) ; v2(45.21,49.4) v2(45.97,49.4) 46.29,49.09 R142.1 45.91,47.75 R141.1 R140.1 R138.1 ; U8.5 45.97,68.58 v2(45.85,68.45) ; v2(11.56,53.85) 11.87,53.53 R136.1 ; v2(49.28,52.45) v2(49.28,53.34) U23.2 ; R99.1 56.07,8.57 55.44,7.94 R100.1 ; v2(17.14,73.79) 17.27,73.66 U11.5 ; v2(54.48,7.11) R100.1 ; R100.1 R101.1 v2(53.34,7.11) ; U9.5 38.73,68.58 v2(38.61,68.45) ; v4(27.81,19.94) 27.75,20 R306.1 ; R239.2 18.35,25.46 ; R98.1 v2(51.69,6.86)
  vias: v2(14.35,57.4) v2(14.35,56.64) v2(52.45,7.11) v2(72.01,68.2) v2(72.77,68.2) v4(10.79,25.4) v4(10.79,24.64) v4(11.56,25.4) v4(11.56,24.64) v4(11.56,23.88) v4(12.45,23.88) v4(17.4,13.08) v4(17.4,12.19) v4(18.16,13.08) v4(18.16,12.19) v4(18.92,13.08) v4(18.92,12.19) v4(26.67,36.45) v4(26.67,35.56) v4(27.43,37.21) v4(27.43,36.45) v4(34.54,74.17) v4(34.54,73.41) v4(35.31,74.17) v4(35.31,73.41) v4(36.07,74.17) v4(36.07,73.41) v4(36.83,74.17) v4(36.83,73.41) v4(62.48,13.08) v4(62.48,12.19) v4(63.37,13.08) v4(63.37,12.19) v4(85.72,36.7) v4(85.72,35.81) v4(86.61,36.7) v4(86.61,35.81)
3.3V_DVDD: length 5.4
  TOP w0.254: v2(70.87,64.14) 71.16,63.84 U3.29
  BOTTOM w0.406: R121.2 R120.2 69.91,63.88
